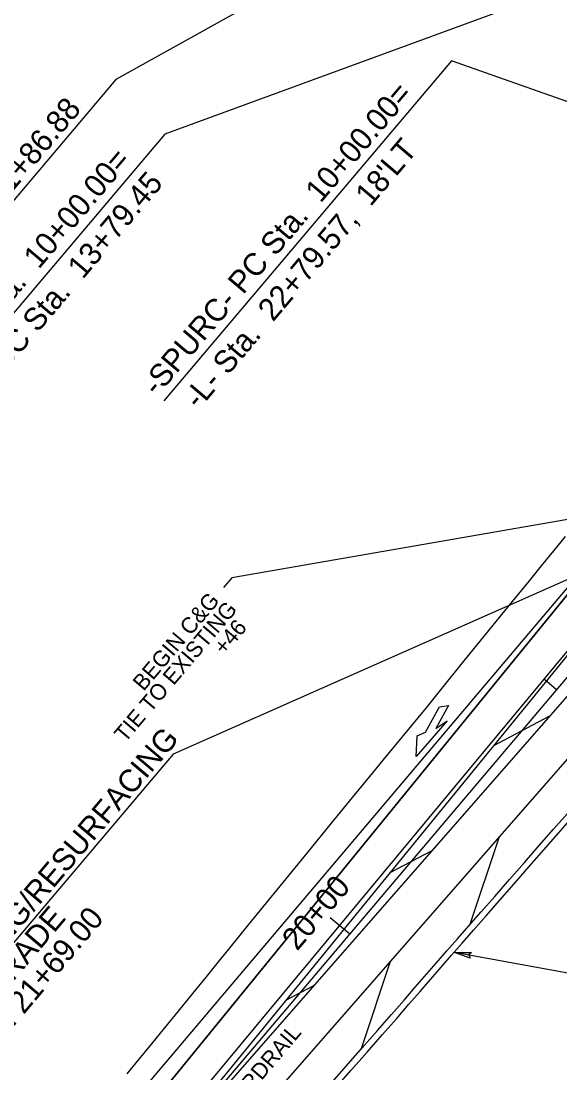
# Model space of a CAD drawing. Extents: x 1761082 to 1764358, y 421907 to 425434.
# Drawn here: x 1761838.2 to 1762006.6, y 422630.5 to 422958.8 of the extents above; entities that cross this region are included whole.
import ezdxf

# ---------------------------------------------------------------- set-up
doc = ezdxf.new("R2010")
doc.units = 0
for name, color, linetype in [('MARK HOOKS CENTER STRAIGHT LEFT TURN ARROW CELL', 7, 'Continuous'), ('MARK HOOKS STRAIGHT RIGHT TURN ARROW CELL', 7, 'Continuous'), ('MARK STRAIGHT RIGHT ARROW CELL', 7, 'Continuous'), ('MARK UTURN ARROW CELL', 7, 'Continuous'), ('Prop Horizontal Alignment Tick Large', 7, 'Continuous'), ('Prop Mkg 3ft Min Skp 3ft Wide White', 7, 'Continuous'), ('Prop Mkg 3ft Min Skp 9ft Wide White', 7, 'Continuous'), ('Prop Mkg Skp Wht', 7, 'Continuous'), ('Prop Mkg Solid White Multiple Diagonals V8i', 7, 'Continuous'), ('Prop Mkg Solid Yel Skip LT', 7, 'Continuous'), ('Prop Mkg Solid Yel Skip RT', 7, 'Continuous'), ('Prop Mkg Solid Yellow Diagonals', 7, 'Continuous'), ('Prop Mkg Solid Yellow Edge Line', 7, 'Continuous'), ('Prop Mkg Solid Yellow Lane Line', 7, 'Continuous'), ('Scratch_Level_0', 7, 'Continuous')]:
    doc.layers.add(name, color=color, linetype=linetype)

msp = doc.modelspace()

# ---------------------------------------------------------------- linework, layer by layer
at = {"layer": 'MARK HOOKS CENTER STRAIGHT LEFT TURN ARROW CELL'}
msp.add_line((1762005.56, 422750.09), (1762001.74, 422753.32), dxfattribs=at)
at = {"layer": 'MARK STRAIGHT RIGHT ARROW CELL'}
msp.add_line((1761294.53, 421910.78), (1762672.97, 423537.92), dxfattribs=at)
at = {"layer": 'MARK UTURN ARROW CELL'}
for points in [[(1762093.81, 423066.09), (1761867.88, 422940.58), (1761783.27, 422840.7)], [(1762157.2, 423023.89), (1761883.16, 422923.48), (1761800.37, 422825.75)], [(1762106.48, 422899.23), (1761972.71, 422946.36), (1761882.86, 422840.3)], [(1762050.16, 422802.74), (1761885.75, 422730.03), (1761804.33, 422633.93)]]:
    msp.add_lwpolyline(points, dxfattribs=at)
at = {"layer": 'Prop Horizontal Alignment Tick Large'}
msp.add_line((1761940.92, 422673.79), (1761934.81, 422678.96), dxfattribs=at)
at = {"layer": 'Prop Mkg 3ft Min Skp 3ft Wide White'}
msp.add_line((1761294.53, 421910.78), (1762672.97, 423537.92), dxfattribs=at)
at = {"layer": 'Prop Mkg 3ft Min Skp 9ft Wide White'}
msp.add_lwpolyline([(1761936.32, 422625.58), (1761941.31, 422631.27), (1761946.33, 422636.98), (1761951.14, 422642.46), (1761955.51, 422647.44), (1761959.44, 422651.94), (1761962.91, 422655.94), (1761969.46, 422663.47), (1761972.76, 422667.26), (1761976.1, 422671.06), (1761979.62, 422675.07), (1761983.5, 422679.49), (1761987.72, 422684.31), (1761992.3, 422689.53), (1761997, 422694.89), (1762001.59, 422700.12), (1762006.07, 422705.23), (1762010.45, 422710.2)], dxfattribs=at)
at = {"layer": 'Prop Mkg Skp Wht'}
for points in [[(1762008.28, 422797.88), (1762004.62, 422793.41), (1762000.78, 422788.74), (1761996.95, 422784.06), (1761993.11, 422779.39), (1761989.28, 422774.71), (1761985.2, 422769.73), (1761980.66, 422764.15), (1761975.64, 422757.96), (1761970.14, 422751.16), (1761964.67, 422744.39), (1761959.7, 422738.3), (1761955.25, 422732.88), (1761951.31, 422728.12), (1761947.07, 422723), (1761941.68, 422716.46), (1761935.17, 422708.51), (1761927.52, 422699.14), (1761920.01, 422689.93), (1761913.92, 422682.45), (1761909.23, 422676.69), (1761903.14, 422669.2), (1761899.84, 422665.15), (1761896.06, 422660.5), (1761891.79, 422655.26), (1761887.36, 422649.83), (1761883.1, 422644.61), (1761879, 422639.59), (1761875.06, 422634.79), (1761871.33, 422630.25)], [(1761934.81, 422626.9), (1761939.81, 422632.59), (1761944.83, 422638.3), (1761949.64, 422643.78), (1761954.01, 422648.76), (1761957.93, 422653.25), (1761961.4, 422657.25), (1761967.95, 422664.79), (1761971.26, 422668.58), (1761974.59, 422672.38), (1761978.12, 422676.39), (1761981.99, 422680.8), (1761986.22, 422685.62), (1761990.79, 422690.85), (1761995.49, 422696.21), (1762000.08, 422701.44), (1762004.57, 422706.55), (1762008.95, 422711.52)]]:
    msp.add_lwpolyline(points, dxfattribs=at)
at = {"layer": 'Prop Mkg Solid White Multiple Diagonals V8i'}
for p, q in [((1761636.39, 422342), (1762107.89, 422898.74)), ((1761847.66, 422582.27), (1762056.32, 422837.86)), ((1761650.04, 422330.43), (1762065.62, 422830.27))]:
    msp.add_line(p, q, dxfattribs=at)
at = {"layer": 'Prop Mkg Solid Yel Skip RT'}
for points in [[(1762013.19, 422803.91), (1761904.06, 422785.03), (1761901.46, 422781.96)], [(1762043.4, 422658.54), (1762041.06, 422655.78), (1761973.71, 422668.13)]]:
    msp.add_lwpolyline(points, dxfattribs=at)
at = {"layer": 'Prop Mkg Solid Yellow Diagonals'}
for p, q in [((1761964.57, 422736.81), (1761969.02, 422744.79)), ((1761971.82, 422745.19), (1761967.82, 422738.02)), ((1761969.02, 422744.79), (1761971.82, 422745.19)), ((1761971.41, 422740.43), (1761961.64, 422729.27)), ((1761967.82, 422738.02), (1761971.41, 422740.43)), ((1761961.64, 422729.27), (1761961.97, 422735.67)), ((1761961.97, 422735.67), (1761964.57, 422736.81))]:
    msp.add_line(p, q, dxfattribs=at)
at = {"layer": 'Prop Mkg Solid Yellow Edge Line'}
msp.add_line((1762055.03, 422836.33), (1761848.88, 422583.77), dxfattribs=at)
at = {"layer": 'Prop Mkg Solid Yellow Lane Line'}
msp.add_lwpolyline([(1761978.57, 422666.34), (1761973.71, 422668.13), (1761978.92, 422668.09), (1761978.11, 422667.32)], close=True, dxfattribs=at)
at = {"layer": 'Scratch_Level_0'}
for p, q in [((1761856.89, 422574.6), (1762095.46, 422846.93)), ((1761842.22, 422538.12), (1762105.31, 422838.44)), ((1761856.89, 422574.6), (1762065.62, 422830.27)), ((1761985.97, 422732.71), (1762003.49, 422741.94)), ((1761987.47, 422703.93), (1761978.49, 422676.81)), ((1761953.57, 422693.02), (1761966.69, 422699.94)), ((1761953.59, 422665.25), (1761944.55, 422637.99)), ((1761921.17, 422653.34), (1761929.9, 422657.94))]:
    msp.add_line(p, q, dxfattribs=at)

# ---------------------------------------------------------------- texts
at = {"layer": 'MARK HOOKS STRAIGHT RIGHT TURN ARROW CELL'}
msp.add_text('20+00', height=7, rotation=49.7301, dxfattribs=at).set_placement((1761924.5, 422668.33))
at = {"layer": 'MARK UTURN ARROW CELL'}
for s, p in [('-SPURC- PC Sta.  10+00.00=', (1761880.73, 422841.43)), ('-SPURC- PT Sta.  11+86.88', (1761781.53, 422841.62)), ("-L- Sta.  22+79.57,  18'LT", (1761893.78, 422837.32)), ('-RPC- PC Sta.  10+00.00=', (1761801.1, 422830.73)), ('-RAB1- PCC Sta.  13+79.45', (1761807.45, 422818.85)), ('END MILLING/RESURFACING', (1761803.54, 422635.04)), ('BEGIN GRADE', (1761810.54, 422629.11)), ('-L- Sta. 21+69.00', (1761817.55, 422623.17))]:
    msp.add_text(s, height=7, rotation=49.7301, dxfattribs=at).set_placement(p)
at = {"layer": 'Prop Mkg Solid Yel Skip LT'}
for s, p in [('BEGIN C&G', (1761876.53, 422749.43)), ('TIE TO EXISTING', (1761870.77, 422733.36)), ('+46', (1761901.77, 422760.67)), ('BEGIN GUARDRAIL', (1761886.23, 422595.93))]:
    msp.add_text(s, height=5, rotation=49.7301, dxfattribs=at).set_placement(p)

doc.saveas('drawing.dxf')
